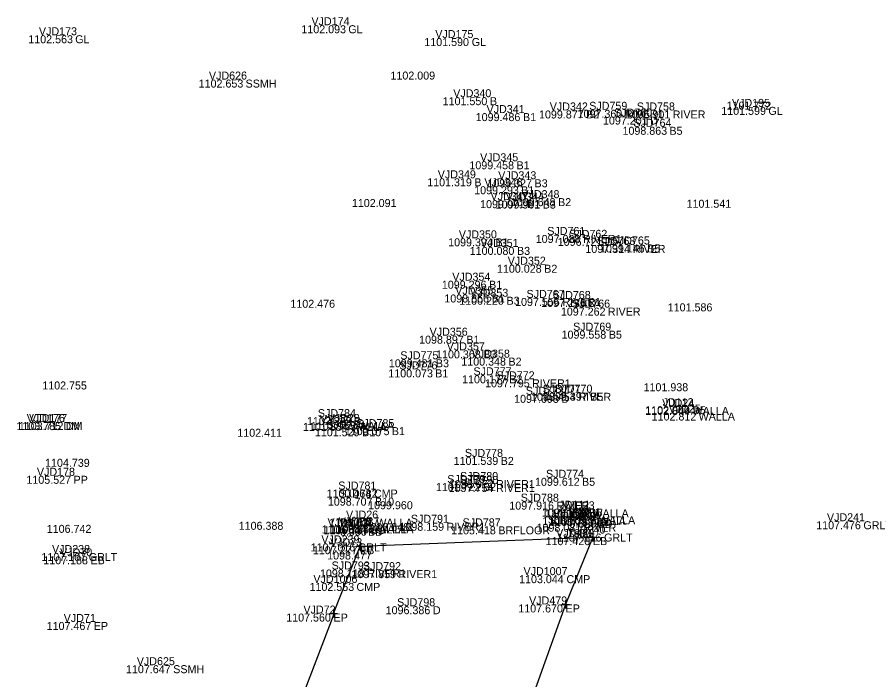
# Model space of a CAD drawing. Extents: x 1629927 to 1630657, y 484405 to 484576.
# Drawn here: x 1630233.2 to 1630340.9, y 484492.8 to 484575.6 of the extents above; entities that cross this region are included whole.
import ezdxf

# ---------------------------------------------------------------- set-up
doc = ezdxf.new("R2010")
doc.units = 0
for name, color, linetype in [('BR_X_SV_Abut_Text', 7, 'Continuous'), ('BR_X_SV_Deck_Floor_Text', 7, 'Continuous'), ('BR_X_SV_Deck_Top_Text', 7, 'Continuous'), ('PV_X_EOP', 7, 'Continuous'), ('SV_X_Shot_Marker', 7, 'Continuous'), ('SV_X_Text_Comment', 7, 'Continuous'), ('SV_X_Text_Elevation', 7, 'Continuous'), ('SV_X_Text_Name', 7, 'Continuous')]:
    doc.layers.add(name, color=color, linetype=linetype)

msp = doc.modelspace()

# ---------------------------------------------------------------- linework, layer by layer
at = {"layer": 'PV_X_EOP'}
msp.add_lwpolyline([(1630272.75, 484501.05), (1630276.06, 484509.47), (1630305.15, 484510.6), (1630301.74, 484502.19), (1630297.37, 484489.97), (1630292.71, 484478.56), (1630290.83, 484473.75), (1630260.38, 484469.01), (1630259.88, 484472.59), (1630263.78, 484477.41), (1630268.33, 484489.25), (1630272.84, 484501.01)], close=True, dxfattribs=at)
at = {"layer": 'SV_X_Shot_Marker'}
for p, q in [((1630304.65, 484510.6), (1630305.65, 484510.6)), ((1630305.15, 484511.1), (1630305.15, 484510.1)), ((1630305.15, 484510.6), (1630305.15, 484510.6)), ((1630275.56, 484509.47), (1630276.56, 484509.47)), ((1630276.06, 484509.97), (1630276.06, 484508.97)), ((1630276.06, 484509.47), (1630276.06, 484509.47)), ((1630301.24, 484502.19), (1630302.24, 484502.19)), ((1630301.74, 484502.69), (1630301.74, 484501.69)), ((1630301.74, 484502.19), (1630301.74, 484502.19)), ((1630272.25, 484501.05), (1630273.25, 484501.05)), ((1630272.75, 484501.55), (1630272.75, 484500.55)), ((1630272.75, 484501.05), (1630272.75, 484501.05))]:
    msp.add_line(p, q, dxfattribs=at)

# ---------------------------------------------------------------- texts
at = {"layer": 'BR_X_SV_Abut_Text'}
for s, p in [('VJD24', (1630313.8, 484526.88)), ('1102.844', (1630311.69, 484525.88)), ('VJD25', (1630314.61, 484526.18)), ('WALLA', (1630317.61, 484525.88)), ('VJD30', (1630271.05, 484524.88)), ('VJD29', (1630272.01, 484525)), ('1102.812', (1630312.49, 484525.18)), ('WALLA', (1630318.36, 484525.18)), ('1101.884', (1630268.93, 484523.88)), ('1101.955', (1630269.91, 484524)), ('WALLA', (1630274.85, 484523.88)), ('WALLA', (1630275.78, 484524)), ('VJD23', (1630301.35, 484514.08)), ('VJD26', (1630274.31, 484512.92)), ('1106.670', (1630299.18, 484513.08)), ('VJD22', (1630300.96, 484513.11)), ('VJD21', (1630302.13, 484513.21)), ('WALLA', (1630305.09, 484513.08)), ('1106.616', (1630272.19, 484511.92)), ('VJD28', (1630273.4, 484512.06)), ('VJD27', (1630274.43, 484512.09)), ('WALLA', (1630278.09, 484511.92)), ('1106.709', (1630298.83, 484512.11)), ('1106.636', (1630299.99, 484512.21)), ('WALLA', (1630304.71, 484512.11)), ('WALLA', (1630305.9, 484512.21)), ('1106.644', (1630271.26, 484511.06)), ('1106.647', (1630272.32, 484511.09)), ('WALLA', (1630277.18, 484511.06)), ('WALLA', (1630278.21, 484511.09))]:
    msp.add_text(s, height=1, dxfattribs=at).set_placement(p)
at = {"layer": 'BR_X_SV_Deck_Floor_Text'}
for s, p in [('SJD787', (1630288.87, 484511.95)), ('1105.418', (1630287.44, 484510.95)), ('BRFLOOR', (1630293.34, 484510.95))]:
    msp.add_text(s, height=1, dxfattribs=at).set_placement(p)
at = {"layer": 'BR_X_SV_Deck_Top_Text'}
for s, p in [('VJD1001', (1630300.22, 484512.99)), ('JD108', (1630301.96, 484512.77)), ('VJD1000', (1630272, 484511.97)), ('JD107', (1630273.31, 484511.78)), ('1106.769', (1630299.7, 484511.99)), ('0.000', (1630302.21, 484511.77)), ('BD', (1630305.58, 484511.99)), ('BD', (1630305.73, 484511.77)), ('1106.787', (1630271.5, 484510.97)), ('0.000', (1630273.56, 484510.78)), ('BD', (1630277.07, 484510.78)), ('BD', (1630277.39, 484510.97))]:
    msp.add_text(s, height=1, dxfattribs=at).set_placement(p)
at = {"layer": 'SV_X_Text_Comment'}
for s, p in [('GL', (1630274.59, 484573.58)), ('GL', (1630240.48, 484572.33)), ('GL', (1630290.01, 484571.98)), ('SSMH', (1630261.76, 484566.79)), ('B', (1630292.29, 484564.59)), ('GL', (1630327.07, 484563.38)), ('B1', (1630296.42, 484562.6)), ('B2', (1630304.31, 484562.93)), ('RIVER1', (1630309.15, 484563.01)), ('D', (1630312.29, 484562.17)), ('RIVER', (1630315.12, 484562.93)), ('B5', (1630314.71, 484560.89)), ('B1', (1630295.61, 484556.58)), ('B', (1630290.34, 484554.45)), ('B1', (1630296.18, 484553.46)), ('B3', (1630297.86, 484554.33)), ('B1', (1630296.94, 484551.72)), ('B3', (1630298.88, 484551.67)), ('B2', (1630300.8, 484551.97)), ('B1', (1630292.99, 484546.95)), ('RIVER1', (1630303.91, 484547.37)), ('D', (1630306.64, 484547.01)), ('B3', (1630295.67, 484545.88)), ('RIVER', (1630310.13, 484546.12)), ('B5', (1630311.94, 484546.18)), ('B2', (1630299.07, 484543.65)), ('B1', (1630292.18, 484541.65)), ('B1', (1630292.5, 484539.93)), ('B3', (1630294.36, 484539.65)), ('RIVER1', (1630301.34, 484539.5)), ('D', (1630304.59, 484539.37)), ('RIVER', (1630307.02, 484538.29)), ('B5', (1630307.14, 484535.41)), ('B1', (1630289.34, 484534.78)), ('B3', (1630291.46, 484532.95)), ('B2', (1630294.6, 484532.04)), ('B3', (1630285.54, 484531.83)), ('B1', (1630285.45, 484530.57)), ('B2', (1630294.7, 484529.83)), ('RIVER1', (1630297.55, 484529.33)), ('RIVER', (1630303.34, 484527.64)), ('B5', (1630304.82, 484527.66)), ('D', (1630301.21, 484527.39)), ('B5', (1630317.61, 484525.97)), ('B', (1630275.29, 484524.6)), ('DM', (1630239, 484523.98)), ('DM', (1630239.3, 484523.99)), ('B1', (1630280.03, 484523.35)), ('B10', (1630276.31, 484523.21)), ('B2', (1630293.63, 484519.63)), ('PP', (1630240.27, 484517.27)), ('B5', (1630303.79, 484517.02)), ('B2', (1630291.41, 484516.36)), ('RIVER1', (1630293.05, 484516.74)), ('RIVER1', (1630293.06, 484516.24)), ('CMP', (1630277.8, 484515.55)), ('B10', (1630277.93, 484514.54)), ('RIVER', (1630300.61, 484514.04)), ('B5', (1630304.7, 484513.16)), ('GRLT', (1630338.95, 484511.59)), ('RIVER1', (1630286.86, 484511.4)), ('RIVER', (1630303.99, 484511.28)), ('EB', (1630305.15, 484509.6)), ('EB', (1630305.15, 484509.6)), ('GRLT', (1630306.55, 484510.05)), ('GRLT', (1630275.8, 484508.82)), ('EB', (1630276.06, 484508.47)), ('GRLT', (1630242.16, 484507.62)), ('EB', (1630242.39, 484507.21)), ('RIVER1', (1630276.95, 484505.56)), ('RIVER1', (1630280.86, 484505.48)), ('CMP', (1630275.61, 484503.88)), ('CMP', (1630301.85, 484504.85)), ('D', (1630285.16, 484500.97)), ('EP', (1630301.74, 484501.19)), ('EP', (1630272.75, 484500.05)), ('EP', (1630242.8, 484499)), ('SSMH', (1630252.72, 484493.6))]:
    msp.add_text(s, height=1, dxfattribs=at).set_placement(p)
at = {"layer": 'SV_X_Text_Elevation'}
for s, p in [('1102.093', (1630268.73, 484573.58)), ('1102.563', (1630234.62, 484572.33)), ('1101.590', (1630284.09, 484571.98)), ('1102.009', (1630279.86, 484567.79)), ('1102.653', (1630255.9, 484566.79)), ('1101.550', (1630286.38, 484564.59)), ('1101.599', (1630321.19, 484563.38)), ('1101.772', (1630321.85, 484564.03)), ('1099.486', (1630290.51, 484562.6)), ('1099.877', (1630298.42, 484562.93)), ('1097.360', (1630303.24, 484563.01)), ('1097.201', (1630306.41, 484562.17)), ('1096.901', (1630309.24, 484562.93)), ('1098.863', (1630308.85, 484560.89)), ('1099.458', (1630289.72, 484556.58)), ('1101.319', (1630284.45, 484554.45)), ('1099.293', (1630290.32, 484553.46)), ('1099.327', (1630291.97, 484554.33)), ('1102.091', (1630275.04, 484551.86)), ('1099.071', (1630291.06, 484551.72)), ('1099.901', (1630293, 484551.67)), ('1099.648', (1630294.9, 484551.97)), ('1101.541', (1630316.85, 484551.77)), ('1099.394', (1630287.07, 484546.95)), ('1097.088', (1630298.01, 484547.37)), ('1096.721', (1630300.76, 484547.01)), ('1100.080', (1630289.76, 484545.88)), ('1097.314', (1630304.21, 484546.12)), ('1099.146', (1630306.04, 484546.18)), ('1100.028', (1630293.17, 484543.65)), ('1099.296', (1630286.28, 484541.65)), ('1098.866', (1630286.59, 484539.93)), ('1100.220', (1630288.45, 484539.65)), ('1097.556', (1630295.43, 484539.5)), ('1102.476', (1630267.36, 484539.27)), ('1097.236', (1630298.69, 484539.37)), ('1101.586', (1630314.5, 484538.82)), ('1097.262', (1630301.15, 484538.29)), ('1099.558', (1630301.24, 484535.41)), ('1098.897', (1630283.44, 484534.78)), ('1100.368', (1630285.56, 484532.95)), ('1100.348', (1630288.71, 484532.04)), ('1099.481', (1630279.66, 484531.83)), ('1100.073', (1630279.59, 484530.57)), ('1100.177', (1630288.81, 484529.83)), ('1102.755', (1630236.36, 484529.06)), ('1097.795', (1630291.68, 484529.33)), ('1101.938', (1630311.48, 484528.84)), ('1098.454', (1630297.42, 484527.64)), ('1099.397', (1630298.93, 484527.66)), ('1097.698', (1630295.31, 484527.39)), ('1102.000', (1630311.69, 484525.97)), ('1102.222', (1630269.42, 484524.6)), ('1103.785', (1630233.13, 484523.98)), ('1103.712', (1630233.43, 484523.99)), ('1100.075', (1630274.16, 484523.35)), ('1102.411', (1630260.73, 484523.15)), ('1101.529', (1630270.42, 484523.21)), ('1104.739', (1630236.71, 484519.39)), ('1101.539', (1630287.75, 484519.63)), ('1105.527', (1630234.38, 484517.27)), ('1099.612', (1630297.92, 484517.02)), ('1101.722', (1630285.54, 484516.36)), ('1097.754', (1630287.14, 484516.24)), ('1098.072', (1630287.18, 484516.74)), ('1100.464', (1630271.88, 484515.55)), ('1098.707', (1630272.04, 484514.54)), ('1099.960', (1630277.07, 484514.09)), ('1097.916', (1630294.71, 484514.04)), ('1098.000', (1630298.79, 484513.16)), ('1106.388', (1630260.9, 484511.52)), ('1098.159', (1630280.98, 484511.4)), ('1107.476', (1630333.05, 484511.59)), ('1106.742', (1630236.92, 484511.14)), ('1098.613', (1630273.12, 484511.13)), ('1098.648', (1630276.62, 484511.36)), ('1098.081', (1630298.11, 484511.28)), ('1107.420', (1630299.24, 484509.6)), ('1107.420', (1630299.24, 484509.6)), ('1107.156', (1630300.65, 484510.05)), ('1107.016', (1630269.89, 484508.82)), ('1107.277', (1630270.17, 484508.47)), ('1107.107', (1630236.26, 484507.62)), ('1107.188', (1630236.49, 484507.21)), ('1098.477', (1630271.95, 484507.81)), ('1098.118', (1630271.05, 484505.56)), ('1097.859', (1630274.98, 484505.48)), ('1102.553', (1630269.75, 484503.88)), ('1103.044', (1630295.93, 484504.85)), ('1096.386', (1630279.26, 484500.97)), ('1107.670', (1630295.83, 484501.19)), ('1107.560', (1630266.84, 484500.05)), ('1107.467', (1630236.91, 484499)), ('1107.647', (1630246.82, 484493.6))]:
    msp.add_text(s, height=1, dxfattribs=at).set_placement(p)
at = {"layer": 'SV_X_Text_Name'}
for s, p in [('VJD174', (1630269.99, 484574.58)), ('VJD173', (1630235.94, 484573.33)), ('VJD175', (1630285.46, 484572.98)), ('VJD626', (1630257.18, 484567.79)), ('VJD340', (1630287.7, 484565.59)), ('VJD195', (1630322.52, 484564.38)), ('VJD341', (1630291.86, 484563.6)), ('VJD342', (1630299.76, 484563.93)), ('SJD759', (1630304.69, 484564.01)), ('SJD760', (1630307.8, 484563.17)), ('SJD758', (1630310.64, 484563.93)), ('SJD764', (1630310.21, 484561.89)), ('VJD345', (1630291.06, 484557.58)), ('VJD349', (1630285.77, 484555.45)), ('VJD346', (1630291.59, 484554.46)), ('VJD343', (1630293.32, 484555.33)), ('VJD347', (1630292.36, 484552.72)), ('VJD344', (1630294.28, 484552.67)), ('VJD348', (1630296.22, 484552.97)), ('SJD761', (1630299.45, 484548.37)), ('SJD762', (1630302.19, 484548.01)), ('VJD350', (1630288.4, 484547.95)), ('SJD763', (1630305.69, 484547.12)), ('SJD765', (1630307.5, 484547.18)), ('VJD351', (1630291.11, 484546.88)), ('VJD352', (1630294.51, 484544.65)), ('VJD354', (1630287.58, 484542.65)), ('VJD355', (1630287.95, 484540.93)), ('VJD353', (1630289.82, 484540.65)), ('SJD767', (1630296.86, 484540.5)), ('SJD768', (1630300.12, 484540.37)), ('SJD766', (1630302.54, 484539.29)), ('SJD769', (1630302.68, 484536.41)), ('VJD356', (1630284.75, 484535.78)), ('VJD357', (1630286.89, 484533.95)), ('VJD358', (1630290.02, 484533.04)), ('SJD775', (1630281.09, 484532.83)), ('SJD776', (1630280.97, 484531.57)), ('SJD777', (1630290.23, 484530.83)), ('SJD772', (1630293.11, 484530.33)), ('SJD771', (1630298.88, 484528.64)), ('SJD770', (1630300.33, 484528.66)), ('SJD773', (1630296.77, 484528.39)), ('JD112', (1630313.86, 484526.97)), ('SJD784', (1630270.79, 484525.6)), ('VJD176', (1630234.42, 484524.98)), ('VJD177', (1630234.72, 484524.99)), ('SJD785', (1630275.59, 484524.35)), ('SJD783', (1630271.87, 484524.21)), ('SJD778', (1630289.16, 484520.63)), ('VJD178', (1630235.69, 484518.27)), ('SJD774', (1630299.29, 484518.02)), ('SJD779', (1630286.96, 484517.36)), ('SJD780', (1630288.56, 484517.74)), ('SJD790', (1630288.58, 484517.24)), ('SJD781', (1630273.34, 484516.55)), ('SJD782', (1630273.49, 484515.54)), ('SJD788', (1630296.14, 484515.04)), ('JD111', (1630300.95, 484514.16)), ('VJD241', (1630334.39, 484512.59)), ('SJD791', (1630282.41, 484512.4)), ('SJD789', (1630299.53, 484512.28)), ('VJD480', (1630300.56, 484510.6)), ('VJD240', (1630301.96, 484511.05)), ('1000', (1630302.02, 484510.6)), ('VJD239', (1630271.23, 484509.82)), ('VJD73', (1630272.32, 484509.47)), ('VJD238', (1630237.58, 484508.62)), ('VJD70', (1630238.59, 484508.21)), ('SJD793', (1630272.51, 484506.56)), ('SJD792', (1630276.42, 484506.48)), ('VJD1007', (1630296.48, 484505.85)), ('VJD1006', (1630270.23, 484504.88)), ('SJD798', (1630280.69, 484501.97)), ('VJD479', (1630297.18, 484502.19)), ('VJD72', (1630268.99, 484501.05)), ('VJD71', (1630239.04, 484500)), ('VJD625', (1630248.17, 484494.6))]:
    msp.add_text(s, height=1, dxfattribs=at).set_placement(p)

doc.saveas('drawing.dxf')
